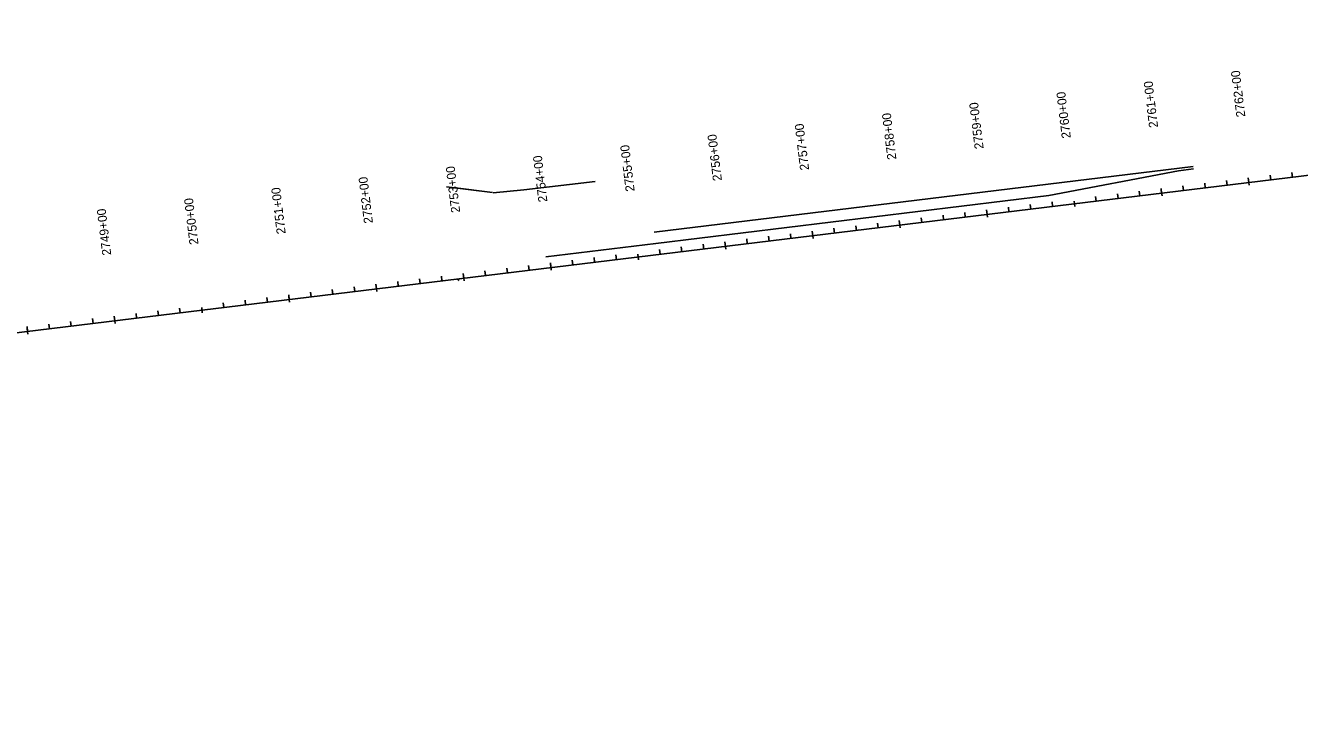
# Model space of a CAD drawing. Extents: x 18432127 to 18439586, y 7649485 to 7650472.
# Drawn here: x 18435853 to 18437302, y 7649488 to 7650289 of the extents above; entities that cross this region are included whole.
import ezdxf

# ---------------------------------------------------------------- set-up
doc = ezdxf.new("R2010")
doc.units = 0
for name, color, linetype in [('MeshTop', 7, 'Continuous'), ('TC_Topsoil', 7, 'Continuous'), ('Terrain', 7, 'Continuous'), ('TL_ForeSlope', 7, 'Continuous'), ('TL_ShoulderTop', 7, 'Continuous'), ('TL_Subgrade', 7, 'Continuous')]:
    doc.layers.add(name, color=color, linetype=linetype)

msp = doc.modelspace()

# ---------------------------------------------------------------- linework, layer by layer
at = {"layer": 'MeshTop'}
for p, q in [((18437294.5, 7650116.1), (18437293.8, 7650121.6)), ((18437170.4, 7650101), (18437169.8, 7650106.4)), ((18437195.2, 7650104.1), (18437194.6, 7650109.5)), ((18437220, 7650107.1), (18437219.4, 7650112.5)), ((18437244.5, 7650113.1), (18437245.2, 7650107.1)), ((18437269.7, 7650113.1), (18437269, 7650118.5)), ((18437071.1, 7650088.9), (18437070.5, 7650094.4)), ((18437096, 7650092), (18437095.3, 7650097.4)), ((18437120.8, 7650095), (18437120.1, 7650100.4)), ((18437145.2, 7650101), (18437146, 7650095)), ((18436922.2, 7650070.8), (18436921.6, 7650076.2)), ((18436946.7, 7650076.9), (18436947.4, 7650070.8)), ((18436971.9, 7650076.8), (18436971.2, 7650082.3)), ((18436996.7, 7650079.9), (18436996, 7650085.3)), ((18437021.5, 7650082.9), (18437020.9, 7650088.3)), ((18437046, 7650088.9), (18437046.7, 7650082.9)), ((18436798.2, 7650055.7), (18436797.5, 7650061.1)), ((18436823, 7650058.7), (18436822.3, 7650064.1)), ((18436847.4, 7650064.8), (18436848.2, 7650058.7)), ((18436872.6, 7650064.7), (18436872, 7650070.2)), ((18436897.4, 7650067.8), (18436896.8, 7650073.2)), ((18436698.9, 7650043.6), (18436698.2, 7650049)), ((18436723.7, 7650046.6), (18436723.1, 7650052)), ((18436748.2, 7650052.7), (18436748.9, 7650046.6)), ((18436773.4, 7650052.6), (18436772.7, 7650058.1)), ((18436574.8, 7650028.5), (18436574.2, 7650033.9)), ((18436599.6, 7650031.5), (18436599, 7650036.9)), ((18436624.5, 7650034.5), (18436623.8, 7650039.9)), ((18436648.9, 7650040.6), (18436649.6, 7650034.5)), ((18436674.1, 7650040.6), (18436673.4, 7650046)), ((18436475.6, 7650016.4), (18436474.9, 7650021.8)), ((18436500.4, 7650019.4), (18436499.7, 7650024.8)), ((18436525.2, 7650022.4), (18436524.5, 7650027.8)), ((18436549.6, 7650028.5), (18436550.4, 7650022.4)), ((18436326.7, 7649998.2), (18436326, 7650003.6)), ((18436351.1, 7650004.3), (18436351.8, 7649998.2)), ((18436376.3, 7650004.3), (18436375.6, 7650009.7)), ((18436401.1, 7650007.3), (18436400.4, 7650012.7)), ((18436425.9, 7650010.3), (18436425.3, 7650015.7)), ((18436450.4, 7650016.4), (18436451.1, 7650010.3)), ((18436202.6, 7649983.1), (18436201.9, 7649988.5)), ((18436227.4, 7649986.1), (18436226.7, 7649991.5)), ((18436251.8, 7649992.2), (18436252.6, 7649986.1)), ((18436277, 7649992.2), (18436276.4, 7649997.6)), ((18436301.8, 7649995.2), (18436301.2, 7650000.6)), ((18436103.3, 7649971), (18436102.6, 7649976.4)), ((18436128.1, 7649974), (18436127.5, 7649979.5)), ((18436152.6, 7649980.1), (18436153.3, 7649974)), ((18436177.8, 7649980.1), (18436177.1, 7649985.5)), ((18435979.2, 7649955.9), (18435978.6, 7649961.3)), ((18436004, 7649958.9), (18436003.4, 7649964.3)), ((18436028.9, 7649961.9), (18436028.2, 7649967.4)), ((18436053.3, 7649968), (18436054, 7649961.9)), ((18436078.5, 7649968), (18436077.8, 7649973.4)), ((18435880, 7649943.8), (18435879.3, 7649949.2)), ((18435904.8, 7649946.8), (18435904.1, 7649952.2)), ((18435929.6, 7649949.8), (18435928.9, 7649955.3)), ((18435954, 7649955.9), (18435954.8, 7649949.8)), ((18435854.8, 7649943.8), (18435855.5, 7649937.7))]:
    msp.add_line(p, q, dxfattribs=at)
at = {"layer": 'TC_Topsoil'}
for p, q in [((18436331.7, 7650105.4), (18436384.2, 7650098.7)), ((18436339.1, 7650104.4), (18436384.2, 7650098.7)), ((18436419.8, 7650102), (18436500.9, 7650111.2)), ((18436419.8, 7650102), (18436500.9, 7650111.2)), ((18436384.9, 7650098.6), (18436419.8, 7650102)), ((18436384.9, 7650098.6), (18436419.8, 7650102))]:
    msp.add_line(p, q, dxfattribs=at)
at = {"layer": 'Terrain'}
msp.add_line((18432137.1, 7649487.7), (18438712.4, 7650288.9), dxfattribs=at)
at = {"layer": 'TL_ForeSlope'}
msp.add_line((18436344.5, 7650000.4), (18436346.3, 7649998.7), dxfattribs=at)
at = {"layer": 'TL_ShoulderTop'}
for p, q in [((18437244.9, 7650110.1), (18437244.2, 7650115.5)), ((18437145.6, 7650098), (18437144.9, 7650103.4)), ((18436947.1, 7650073.8), (18436946.4, 7650079.2)), ((18437046, 7650088.9), (18437046.7, 7650082.9)), ((18436847.8, 7650061.7), (18436847.1, 7650067.1)), ((18436748.5, 7650049.6), (18436747.9, 7650055)), ((18436649.3, 7650037.5), (18436648.6, 7650042.9)), ((18436450.7, 7650013.3), (18436450.1, 7650018.8)), ((18436549.6, 7650028.5), (18436550.4, 7650022.4)), ((18436351.5, 7650001.2), (18436350.8, 7650006.7)), ((18436252.2, 7649989.1), (18436251.5, 7649994.6)), ((18436152.9, 7649977.1), (18436152.3, 7649982.5)), ((18436053.3, 7649968), (18436054, 7649961.9)), ((18435855.1, 7649940.8), (18435854.5, 7649946.2)), ((18435954.4, 7649952.9), (18435953.7, 7649958.3))]:
    msp.add_line(p, q, dxfattribs=at)
at = {"layer": 'TL_Subgrade'}
for p, q in [((18436568.3, 7650053.9), (18437181.3, 7650128.5)), ((18437164.8, 7650123.5), (18437017.1, 7650095.4)), ((18437181.7, 7650125.6), (18437164.8, 7650123.5)), ((18437017.1, 7650095.4), (18436569.9, 7650041)), ((18436444.9, 7650025.7), (18436569.9, 7650041))]:
    msp.add_line(p, q, dxfattribs=at)

# ---------------------------------------------------------------- texts
at = {"layer": 'MeshTop'}
for s, p in [('2762+00', (18437240.9, 7650185.2)), ('2761+00', (18437141.6, 7650173.1)), ('2760+00', (18437042.3, 7650161)), ('2759+00', (18436943.1, 7650148.9)), ('2757+00', (18436744.5, 7650124.7)), ('2758+00', (18436843.8, 7650136.8)), ('2756+00', (18436645.3, 7650112.6)), ('2755+00', (18436546, 7650100.5)), ('2754+00', (18436446.7, 7650088.4)), ('2753+00', (18436347.5, 7650076.3)), ('2751+00', (18436148.9, 7650052.1)), ('2752+00', (18436248.2, 7650064.2)), ('2750+00', (18436049.7, 7650040)), ('2749+00', (18435950.4, 7650027.9))]:
    msp.add_text(s, height=10.2, rotation=96.947, dxfattribs=at).set_placement(p)
at = {"layer": 'TL_ShoulderTop'}
for s, p in [('2760+00', (18437042.3, 7650161)), ('2755+00', (18436546, 7650100.5)), ('2750+00', (18436049.7, 7650040))]:
    msp.add_text(s, height=10.2, rotation=96.947, dxfattribs=at).set_placement(p)

doc.saveas('drawing.dxf')
